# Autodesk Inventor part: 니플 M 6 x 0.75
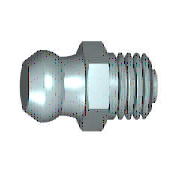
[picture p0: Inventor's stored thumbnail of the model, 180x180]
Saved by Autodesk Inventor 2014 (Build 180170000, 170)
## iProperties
IsCustomPart: 1
Created: 2012-02
Part Number: 니플 M 6 x 0.75
Material: 강철, 연강
Description: 윤활 니플, 원추 유형 A
Document SubType Name: Modeling
Standard: JIS B 1575
Designer: mduedu
Standards Organization: JIS
Language: ko-KR
Size Designation: MT 6 x 0.75
Categories: <MemberInstance><Categories><Category DisplayName="기타 부품" InternalName="5aa15e00-363f-49f2-933f-16f664388e3f" Mnemonic="OTHER"><Category DisplayName="그리스 부속품" I
Density: 1 g/cm^3
Appearance: 강철
Author: mduedu
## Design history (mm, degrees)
sketch "스케치1"
  geometry: L1 (-8.8, 0)-(-8.8, 2.4); L2 (-8.8, 2.4)-(-7.335, 3.202); L3 (-8.8, 0)-(4.7, 0); L4 (4.7, 0)-(4.7, 1.5); L5 (4.7, 1.5)-(4, 1.5); L6 (4, 1.5)-(4, 3); L7 (4, 3)-(0, 3); L8 (-11.5, 0)-(7.4, 0) reference; L9 (0, -1.733)-(0, 10.398) reference; L10 (-3, 3.5)-(0, 3.5); L11 (0, 3.5)-(0, 3); A1 r 3.3 centre (-6.535, 0) between (-4.789, 2.8) and (-7.335, 3.202); A2 r 6 centre (-6.053, 8.665) between (-4.789, 2.8) and (-3, 3.5)
  constraints: 18 end point, 5 perpendicular, 4 point on circle, 2 centre point, 2 parallel, 2 point on line, 1 collinear, 1 vertical
  dimensions: "d0" = 13.5 distance between parallel lines of L1 L4 (= GL); "d1" = 5.6 diameter of A1.start L3 (= KGB2); "d2" = 0.7 distance between parallel lines of L4 L6 (= PHH); "d3" = 3 diameter of L5 L3 (= 0.5 x NND); "d4" = 6 diameter of L7 L3 (= NND); "d5" = 6.6 dimension on A1 L3 (= KR); "d6" = 4.8 diameter of L1.end L3 (= KGB1); "d7" = 6 radius of A2 (= RBN); "d11" = 7 diameter of L10.start L3 (= SW); "d14" = 3 distance of L10.start L10.end (= KOH); "d15" = 4 distance between parallel lines of L6 L11 (= NLG); "d61" = 7.33505 distance from line of L9 L2.end (computed from KGB1, KR, PHH, GL, NLG, VERS); "d62" = 6.53505 distance from line of L9 A1.centre (computed from NLG, GL, PHH, KR, KGB1)
revolve "본체" sketch "스케치1" stored, may be unused: angle "d25" = 90 deg
sketch "스케치2"
  geometry: L1 (2.021, 3.5)-(4.041, 0); L2 (4.041, 0)-(2.021, -3.5); L3 (2.021, -3.5)-(-2.021, -3.5); L4 (-2.021, -3.5)-(-4.041, 0); L5 (-4.041, 0)-(-2.021, 3.5); L6 (-2.021, 3.5)-(2.021, 3.5); C1 r 3.5 at (0, 0) reference; 1 further point
  constraints: 12 end point, 1 coincident, 1 horizontal, 1 tangent, 11 other
extrude "머리" join sketch "스케치2" distance "d17" = 3 (= KOH); taper "d18" = 0 deg
sketch "스케치3"
  geometry: L1 (2.687, 4.041)-(3, 4.041); L2 (3, 4.041)-(3, 3.5); L3 (3, 3.5)-(2.687, 4.041); L4 (0.313, 4.041)-(0, 4.041); L5 (0, 4.041)-(0, 3.5); L6 (0, 3.5)-(0.313, 4.041); L7 (3.6, 0)-(-0.6, 0) reference; L8 (0, 4.041)-(0, 2.021) reference; L9 (0, 4.041)-(3, 4.041) reference; L10 (3, 3.031)-(3, 4.041) reference
  constraints: 12 end point, 4 collinear, 3 perpendicular, 1 horizontal
  dimensions: "d19" = 3.5 distance from line of L5.end L7 (= 0.5 x SW); "d20" = 3.5 distance from line of L2.end L7 (= 0.5 x SW); "d21" = 30 deg angle of L6 L5; "d22" = 30 deg angle of L2 L3
revolve "모따기1" sketch "스케치3" stored, may be unused: angle "d56" = 90 deg
body "Solid1"
fillet "모깎기1" dims "d8" = 0.2 (= RR)
feature "스레드1" dims "d9" = 3.53991 (= NLG - GAL), "d10" = 0
chamfer "모따기2" distance "d23" = 0.46009 (= -0.5 x GD1 + 0.5 x NND); stored, may be unused: angle "d24" = 45 deg, second distance "d59" = 0.46009 (= -0.5 x GD1 + 0.5 x NND)
other parameters: "NLG" = 4 [user parameter; used in 4 equation terms], "GL" = 13.5 [user parameter; used in 3 equation terms], "NND" = 6 [user parameter; used in 4 equation terms], "KGB1" = 4.8 [user parameter; used in 3 equation terms], "KGB2" = 5.6 [user parameter; used in 1 equation term], "VERS" = 0.8 [user parameter; used in 1 equation term], "KR" = 6.6 [user parameter; used in 3 equation terms], "RBN" = 6 [user parameter; used in 1 equation term], "SW" = 7 [user parameter; used in 3 equation terms], "KOH" = 3 [user parameter; used in 2 equation terms], "GAL" = 0.46009 (= 0.61345 x PTC) [user parameter; used in 1 equation term], "FAWI" = 45 deg [user parameter], "PHH" = 0.7 [user parameter; used in 3 equation terms], "GD1" = 5.07983 (= THREADDIA - 1.2269 x PTC) [user parameter; used in 2 equation terms], "RR" = 0.2 [user parameter; used in 1 equation term], "d12" = 0, "d13" = 0, "GUL" = 0.46009 (= 0.61345 x PTC) [user parameter], "TPU" = 13.33333 (computed from PTC) [user parameter], "DULO" = 1.5 [user parameter], "PTC" = 0.75 [user parameter; used in 4 equation terms], "GEL" = 4 [user parameter], "THREADDIA" = 6 [user parameter; used in 1 equation term], "TOA" = 30 deg [user parameter]
